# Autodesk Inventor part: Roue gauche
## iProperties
Author: Flavien MARTY
Shininess: 20.0
PropertySet Name: _Private Model Information
Created: 2001-10
Part Number: Roue gauche
Material: Par défaut
Document SubType Name: Modélisation
Designer: Flavien MARTY
Control State: 0
Master: False
Checked Out: False
PropertySet Name: Design Tracking Control
Density: 0.0
Volumn: 0.0
Area: 0.0
PropertySet Name: Model Information
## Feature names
1. Base1
